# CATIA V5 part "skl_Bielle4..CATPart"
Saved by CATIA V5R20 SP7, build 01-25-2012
Part number: skl_Bielle4
Publications: "Axe_Bielle4Equerre6", "Axe_Bielle4Levier1", "Point.1", "Point.2", "Plan.1"
Bounding box of the stored display mesh (mm): x 0 to 20, y 0 to 10.033, z 123.588 to 152
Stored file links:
  J:\ACHTUNG2\skl_Bielle4..CATPart
  J:\cmilovidofIAO\skl_IAO.CATProduct
  J:\ACHTUNG2\skl_IAO2.CATProduct
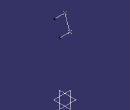
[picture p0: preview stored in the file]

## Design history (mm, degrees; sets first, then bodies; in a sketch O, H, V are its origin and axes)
Set1
  Point1: linked copy from another document
  Point2: linked copy from another document
  Plane1: linked copy from another document
Body1 (main body)
  Line1: type PtPt, FirstPoint Point1, SecondPoint Point2
  Line2: type Normal, RefPoint Point2, RefSkin Plane1, Start 0, End 20
  Line3: type Normal, RefPoint Point1, RefSkin Plane1, Start 0, End 20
